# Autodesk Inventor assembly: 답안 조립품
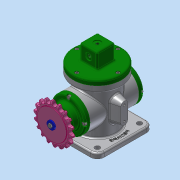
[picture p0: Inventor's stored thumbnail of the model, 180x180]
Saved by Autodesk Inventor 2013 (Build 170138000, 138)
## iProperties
Created: 2021-03
Part Number: 답안 조립품
Document SubType Name: Assembly
Designer: Administrator
Author: Administrator
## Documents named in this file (19)
- C:\Users\Administrator\Desktop\710306v1003\답안 조립품.iam
- C:\Users\Administrator\Desktop\710306v1003\본체.ipt
- C:\Users\Administrator\Desktop\710306v1003\앞커버.ipt
- C:\Users\Administrator\Desktop\710306v1003\베어링 17 x 40 x 12.ipt
- C:\Users\Administrator\Desktop\710306v1003\오일 실 17 30 8.ipt
- C:\Users\Administrator\Desktop\710306v1003\뒤커버.ipt
- C:\Users\Administrator\Desktop\710306v1003\볼트 M4 x 10.ipt
- C:\Users\Administrator\Desktop\710306v1003\편심축.ipt
- C:\Users\Administrator\Desktop\710306v1003\멈춤나사 M3.ipt
- C:\Users\Administrator\Desktop\710306v1003\스프로킷.ipt
- C:\Users\Administrator\Desktop\710306v1003\키 4 x 4 x 12.ipt
- C:\Users\Administrator\Desktop\710306v1003\볼트 M4 x 8.ipt
- C:\Users\Administrator\Desktop\710306v1003\와셔 4x16.ipt
- C:\Users\Administrator\Desktop\710306v1003\덮개.ipt
- C:\Users\Administrator\Desktop\710306v1003\E-링.ipt
- C:\Users\Administrator\Desktop\710306v1003\링크.ipt
- C:\Users\Administrator\Desktop\710306v1003\슬라이더.ipt
- C:\Users\Administrator\Desktop\710306v1003\클레비스 핀 6 x 22.ipt
- 클레비스 핀 6 x 22.ipt
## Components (1 placed, 1 different names)
1. E-링:1
